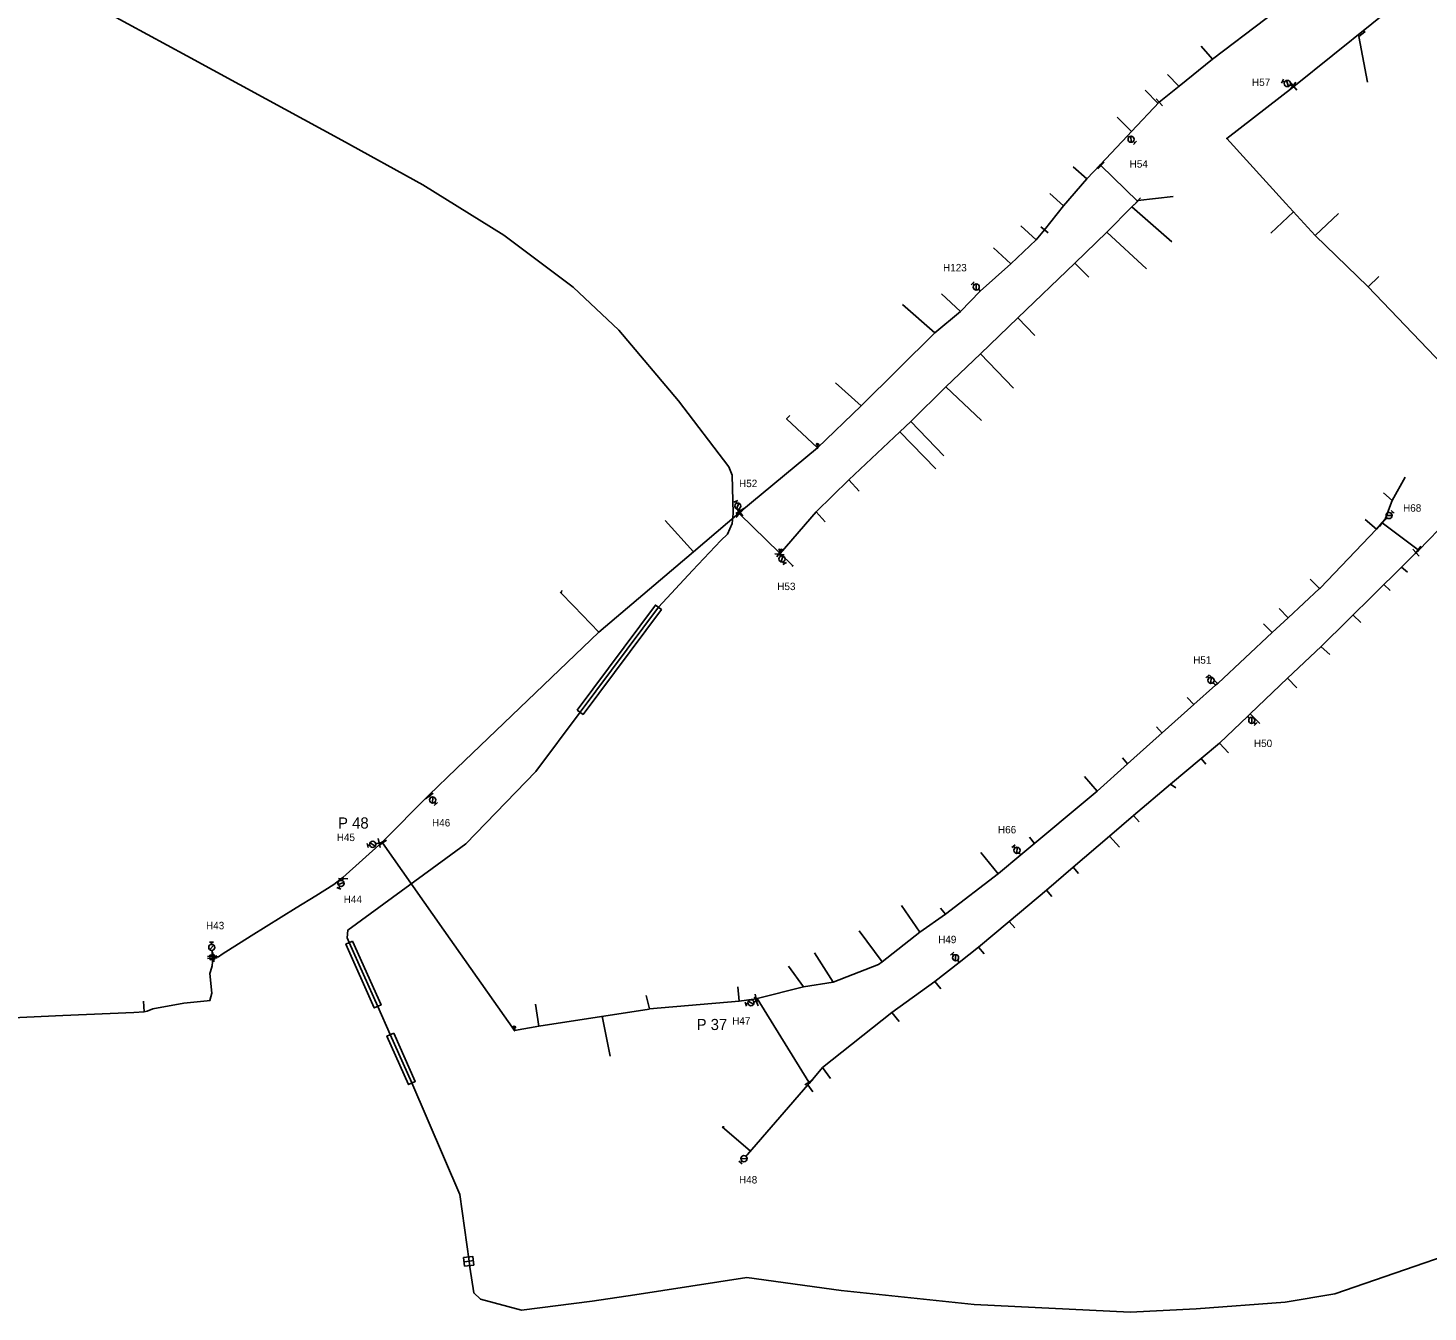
# Model space of a CAD drawing. Extents: x -548873 to -538270, y -1201997 to -1192514.
# Drawn here: x -546483.2 to -546105.6, y -1194944.2 to -1194597.8 of the extents above; entities that cross this region are included whole.
import ezdxf

# ---------------------------------------------------------------- set-up
doc = ezdxf.new("R2010")
doc.units = 0
for name, color, linetype in [('KN_HRAN_STÁTNÍ', 7, 'Continuous'), ('KN_PARC_Č', 7, 'Continuous'), ('KN_VKP_HRAN_SPORNÁ', 7, 'Continuous'), ('PK_HRAN_SPORNÁ', 7, 'Continuous'), ('PK_PARC_Čv', 7, 'Continuous'), ('Vrstva 29', 7, 'Continuous'), ('Vrstva 37', 7, 'Continuous'), ('Vrstva 39', 7, 'Continuous')]:
    doc.layers.add(name, color=color, linetype=linetype)

# ---------------------------------------------------------------- blocks, each defined once
blk = doc.blocks.new('160')
at = {"layer": 'KN_HRAN_STÁTNÍ'}
blk.add_circle((0, 0), 0.0458, dxfattribs=at)
blk = doc.blocks.new('147')
at = {"layer": 'KN_HRAN_STÁTNÍ'}
blk.add_line((0, 1.27), (0, -1.27), dxfattribs=at)
blk = doc.blocks.new('133')
at = {"layer": 'KN_HRAN_STÁTNÍ'}
for p, q in [((0.28, 0), (0, 0)), ((0.54, 0.58), (1.7, -0.58)), ((1.94, 0), (2.52, 0)), ((2.52, 0.58), (2.52, -0.58))]:
    blk.add_line(p, q, dxfattribs=at)
blk.add_circle((1.11, 0), 0.825, dxfattribs=at)
blk = doc.blocks.new('150')
at = {"layer": 'KN_HRAN_STÁTNÍ'}
blk.add_line((0, 1.27), (0, -1.27), dxfattribs=at)
blk = doc.blocks.new('128')
at = {"layer": 'KN_HRAN_STÁTNÍ'}
for p, q in [((-0.19, 1.06), (-0.43, 1.15)), ((-0.36, 0.84), (-0.19, 1.06)), ((-0.19, 1.06), (-0.02, 1.25)), ((-0.19, 1.06), (0, 0)), ((0.05, 0.95), (-0.19, 1.06)), ((-0.1, 1), (0.41, 0.91)), ((-0.07, 0.82), (0.17, 0.96)), ((0.17, 0.96), (-0.02, 1.13)), ((0.17, 0.96), (0, 0)), ((0.19, 1.21), (0.17, 0.96)), ((0.17, 0.96), (0.38, 1.08)), ((0.36, 0.77), (0.17, 0.96))]:
    blk.add_line(p, q, dxfattribs=at)

msp = doc.modelspace()

# ---------------------------------------------------------------- linework, layer by layer
at = {"layer": 'KN_PARC_Č'}
for points in [[(-546122.986, -1194598.456), (-546122.633, -1194598.83), (-546124.253, -1194600.048), (-546121.876, -1194612.409)], [(-546163.743, -1194606.156), (-546166.826, -1194602.721)], [(-546172.771, -1194613.509), (-546175.878, -1194610.38)], [(-546178.408, -1194618.175), (-546181.873, -1194614.569)], [(-546185.564, -1194625.718), (-546189.41, -1194621.875)], [(-546197.613, -1194638.468), (-546201.281, -1194635.229)], [(-546203.895, -1194645.758), (-546207.653, -1194642.446)], [(-546184.057, -1194644.482), (-546183.87, -1194644.37), (-546174.31, -1194643.22)], [(-546185.481, -1194646.007), (-546174.686, -1194655.498)], [(-546141.867, -1194647.364), (-546148.008, -1194653.176)], [(-546135.992, -1194653.742), (-546129.778, -1194647.874)], [(-546211.32, -1194654.964), (-546215.469, -1194651.136)], [(-546192.274, -1194652.901), (-546181.503, -1194662.751)], [(-546218.09, -1194661.404), (-546222.809, -1194657.141)], [(-546200.907, -1194661.253), (-546197.102, -1194665.049)], [(-546121.754, -1194667.633), (-546118.825, -1194664.814)], [(-546231.675, -1194674.228), (-546236.854, -1194669.543)], [(-546238.662, -1194680.015), (-546247.341, -1194672.412)], [(-546216.268, -1194676.004), (-546211.634, -1194680.771)], [(-546226.313, -1194685.65), (-546217.446, -1194694.965)], [(-546258.544, -1194699.677), (-546265.398, -1194693.53)], [(-546235.698, -1194694.605), (-546226.069, -1194703.721)], [(-546270.271, -1194711.09), (-546278.627, -1194703.224), (-546277.766, -1194702.301)], [(-546248.046, -1194706.704), (-546238.332, -1194716.698)], [(-546245.115, -1194703.951), (-546236.198, -1194713.176)], [(-546115.221, -1194725.284), (-546111.778, -1194718.979)], [(-546261.859, -1194719.676), (-546259.078, -1194722.71)], [(-546116.917, -1194730.186), (-546117.09, -1194730.018), (-546115.221, -1194725.284), (-546117.591, -1194723.222)], [(-546270.667, -1194728.284), (-546268.225, -1194730.992)], [(-546303.763, -1194739.095), (-546311.34, -1194730.65)], [(-546119.495, -1194732.956), (-546122.532, -1194730.391)], [(-546280.54, -1194739.38), (-546276.977, -1194742.888), (-546276.903, -1194742.82), (-546276.835, -1194742.894)], [(-546276.977, -1194742.888), (-546277.043, -1194742.963), (-546276.975, -1194743.036)], [(-546112.743, -1194743.216), (-546111.09, -1194744.591)], [(-546134.841, -1194749.019), (-546137.394, -1194746.495)], [(-546117.473, -1194747.911), (-546115.785, -1194749.567)], [(-546329.307, -1194760.744), (-546336.039, -1194753.781), (-546339.713, -1194749.945)], [(-546339.406, -1194750.266), (-546339.203, -1194749.54)], [(-546143.338, -1194756.926), (-546145.724, -1194754.403)], [(-546125.826, -1194756.202), (-546123.741, -1194758.129)], [(-546147.621, -1194760.91), (-546149.995, -1194758.488)], [(-546134.382, -1194764.695), (-546132.11, -1194766.84)], [(-546162.378, -1194774.635), (-546164.512, -1194772.411)], [(-546143.472, -1194773.159), (-546140.982, -1194775.757)], [(-546168.729, -1194780.313), (-546170.531, -1194778.423)], [(-546153.531, -1194782.778), (-546150.959, -1194785.389)], [(-546177.348, -1194788.02), (-546178.805, -1194786.356)], [(-546161.842, -1194790.712), (-546159.438, -1194793.34)], [(-546186.618, -1194796.308), (-546187.977, -1194794.661)], [(-546166.808, -1194794.883), (-546165.489, -1194796.415)], [(-546194.842, -1194803.658), (-546198.271, -1194799.72)], [(-546175.035, -1194801.793), (-546173.617, -1194802.8)], [(-546185.065, -1194810.22), (-546183.481, -1194811.951)], [(-546211.729, -1194817.756), (-546213.104, -1194816.118)], [(-546191.53, -1194815.782), (-546188.808, -1194818.78)], [(-546221.534, -1194825.94), (-546226.201, -1194820.236)], [(-546201.292, -1194824.178), (-546199.867, -1194825.921)], [(-546208.497, -1194830.375), (-546207.108, -1194832.062)], [(-546242.708, -1194841.687), (-546247.597, -1194834.516)], [(-546235.789, -1194836.871), (-546237.065, -1194835.268)], [(-546218.534, -1194838.815), (-546217.067, -1194840.498)], [(-546252.876, -1194849.682), (-546259.028, -1194841.391)], [(-546266.096, -1194855.173), (-546271.099, -1194847.246)], [(-546226.831, -1194845.794), (-546225.348, -1194847.523)], [(-546274.08, -1194856.427), (-546278.137, -1194850.861)], [(-546315.58, -1194862.436), (-546316.502, -1194858.753)], [(-546291.379, -1194860.351), (-546291.804, -1194856.479)], [(-546238.614, -1194855.023), (-546237.043, -1194857.026)], [(-546451.932, -1194863.229), (-546452.128, -1194860.291)], [(-546345.493, -1194867.09), (-546346.31, -1194861.12)], [(-546328.334, -1194864.416), (-546326.184, -1194875.204)], [(-546250.214, -1194863.344), (-546248.207, -1194865.843)], [(-546268.914, -1194878.261), (-546266.808, -1194881.224)], [(-546272.858, -1194882.905), (-546271.514, -1194884.812)], [(-546288.366, -1194900.764), (-546296.024, -1194894.205)], [(-546295.644, -1194894.53), (-546295.601, -1194894.022)]]:
    msp.add_lwpolyline(points, dxfattribs=at)
at = {"layer": 'KN_VKP_HRAN_SPORNÁ'}
for points in [[(-546141.811, -1194613.588), (-546120.765, -1194596.671), (-546115.756, -1194592.647), (-546107.535, -1194586.111), (-546091.8, -1194574.383), (-546081.422, -1194567.518), (-546074.38, -1194562.881), (-546061.572, -1194555.512), (-546054.438, -1194551.591), (-546051.299, -1194549.866), (-546041.333, -1194544.088), (-546029.151, -1194537.503), (-546017.951, -1194531.352), (-546014.467, -1194529.438), (-546003.219, -1194523.26), (-545995.607, -1194519.528), (-545984.581, -1194513.447), (-545967.893, -1194504.829), (-545932.842, -1194488.164), (-545928.87, -1194485.6)], [(-546126.397, -1194578.01), (-546136.167, -1194585.394), (-546149.224, -1194595.263), (-546163.743, -1194606.156), (-546172.754, -1194613.495), (-546178.09, -1194617.84)], [(-546159.838, -1194627.61), (-546141.901, -1194613.661), (-546141.811, -1194613.588)], [(-546178.09, -1194617.84), (-546185.563, -1194625.717), (-546186.67, -1194626.889), (-546194.034, -1194634.68)], [(-546086.47, -1194702.96), (-546103.514, -1194686.669), (-546103.668, -1194686.508), (-546121.816, -1194667.569), (-546135.992, -1194653.742), (-546143.948, -1194645.105), (-546159.838, -1194627.61)], [(-546194.034, -1194634.68), (-546197.613, -1194638.468), (-546203.895, -1194645.758), (-546209.04, -1194652.27)], [(-546194.034, -1194634.68), (-546193.82, -1194634.89)], [(-546193.82, -1194634.89), (-546183.999, -1194644.539)], [(-546183.999, -1194644.539), (-546183.936, -1194644.601), (-546185.481, -1194646.007), (-546192.274, -1194652.901), (-546200.907, -1194661.253), (-546216.268, -1194676.004), (-546226.312, -1194685.649), (-546235.691, -1194694.598), (-546245.114, -1194703.95), (-546248.046, -1194706.703), (-546261.859, -1194719.676), (-546270.667, -1194728.284), (-546280.358, -1194739.557)], [(-546209.04, -1194652.27), (-546211.319, -1194654.963), (-546218.087, -1194661.401), (-546226.373, -1194668.799), (-546231.675, -1194674.228), (-546238.662, -1194680.015), (-546258.544, -1194699.677), (-546270.244, -1194711.067)], [(-546270.244, -1194711.067), (-546291.22, -1194728.45)], [(-546291.534, -1194728.712), (-546303.758, -1194739.09)], [(-546291.22, -1194728.45), (-546291.534, -1194728.712)], [(-546291.35, -1194728.89), (-546291.534, -1194728.712)], [(-546280.54, -1194739.38), (-546291.35, -1194728.89)], [(-546117.978, -1194731.239), (-546116.913, -1194730.182)], [(-546108.134, -1194738.726), (-546099.982, -1194730.283)], [(-546286.559, -1194859.614), (-546274.08, -1194856.427), (-546266.095, -1194855.173), (-546266.017, -1194855.161), (-546253.86, -1194850.456), (-546252.877, -1194849.683), (-546242.708, -1194841.687), (-546235.786, -1194836.869), (-546221.498, -1194825.912), (-546215.443, -1194820.857), (-546194.843, -1194803.659), (-546186.618, -1194796.308), (-546168.731, -1194780.315), (-546162.922, -1194775.122), (-546162.381, -1194774.638), (-546162.227, -1194774.5), (-546147.621, -1194760.91), (-546143.338, -1194756.926), (-546134.841, -1194749.019), (-546134.724, -1194748.911), (-546119.495, -1194732.956), (-546117.978, -1194731.239)], [(-546117.978, -1194731.239), (-546117.95, -1194731.26)], [(-546117.95, -1194731.26), (-546108.295, -1194738.609)], [(-546303.758, -1194739.09), (-546329.307, -1194760.744)], [(-546280.54, -1194739.38), (-546280.358, -1194739.557)], [(-546272.438, -1194882.421), (-546268.908, -1194878.254), (-546250.214, -1194863.344), (-546238.614, -1194855.023), (-546232.028, -1194849.859), (-546226.83, -1194845.793), (-546218.535, -1194838.816), (-546208.497, -1194830.375), (-546201.292, -1194824.178), (-546191.532, -1194815.783), (-546185.065, -1194810.22), (-546175.034, -1194801.792), (-546166.808, -1194794.883), (-546161.842, -1194790.712), (-546161.722, -1194790.611), (-546154.291, -1194783.505), (-546153.531, -1194782.778), (-546143.472, -1194773.159), (-546134.374, -1194764.687), (-546112.744, -1194743.217), (-546108.807, -1194739.309)], [(-546108.807, -1194739.309), (-546108.134, -1194738.726)], [(-546108.295, -1194738.609), (-546108.134, -1194738.726)], [(-546329.307, -1194760.744), (-546367.632, -1194797.587), (-546375.109, -1194804.775), (-546387.734, -1194817.409)], [(-546387.734, -1194817.409), (-546398.318, -1194827)], [(-546387.734, -1194817.409), (-546387.6, -1194817.63)], [(-546387.6, -1194817.63), (-546371.035, -1194841.207), (-546352.031, -1194868.254)], [(-546398.318, -1194827), (-546400.74, -1194828.82), (-546405.63, -1194831.94), (-546410.91, -1194835.12), (-546423.01, -1194842.72), (-546430.87, -1194847.61), (-546431.87, -1194848.33), (-546431.94, -1194848.35), (-546432.725, -1194848.39), (-546433.27, -1194848.42)], [(-546433.56, -1194848.16), (-546433.603, -1194847.112)], [(-546487.382, -1194864.802), (-546473.827, -1194864.211), (-546454.657, -1194863.363), (-546451.932, -1194863.229), (-546451.08, -1194862.99), (-546449.54, -1194862.42), (-546441.25, -1194860.87), (-546434.88, -1194860.24), (-546434.166, -1194860.169), (-546433.7, -1194858.21), (-546434.19, -1194852.88), (-546433.98, -1194852.29), (-546433.56, -1194850.76), (-546433.493, -1194849.74), (-546433.501, -1194849.449), (-546433.52, -1194848.74)], [(-546433.54, -1194848.46), (-546433.56, -1194848.16)], [(-546433.27, -1194848.42), (-546433.54, -1194848.46)], [(-546433.52, -1194848.74), (-546433.54, -1194848.46)], [(-546352.031, -1194868.254), (-546345.493, -1194867.09), (-546315.687, -1194862.445), (-546315.58, -1194862.436), (-546291.379, -1194860.351), (-546286.856, -1194859.659)], [(-546286.856, -1194859.659), (-546286.559, -1194859.614)], [(-546272.576, -1194882.196), (-546286.559, -1194859.614)], [(-546289.261, -1194901.795), (-546289.184, -1194901.707), (-546272.858, -1194882.905), (-546272.438, -1194882.421)], [(-546272.576, -1194882.196), (-546272.438, -1194882.421)]]:
    msp.add_lwpolyline(points, dxfattribs=at)
at = {"layer": 'PK_HRAN_SPORNÁ'}
for points in [[(-546364.251, -1194930.494), (-546366.75, -1194912.52), (-546379.68, -1194882.4), (-546385.51, -1194869.33), (-546388.91, -1194861.76), (-546396.58, -1194844.54), (-546397.132, -1194843.25), (-546396.96, -1194841.17), (-546370.57, -1194821.84), (-546365.1, -1194817.88), (-546346.25, -1194798.34), (-546334.333, -1194782.39), (-546313.18, -1194754.08), (-546303.96, -1194744.18), (-546296.32, -1194736.07), (-546294.54, -1194734.33), (-546293.34, -1194731.48), (-546292.99, -1194728.78), (-546293.31, -1194718.42), (-546294.16, -1194716.21), (-546307.73, -1194698.38), (-546323.83, -1194679.28), (-546336.23, -1194667.67), (-546354.85, -1194653.7), (-546376.78, -1194640.1), (-546398.61, -1194628.04), (-546419.12, -1194616.9), (-546440.4, -1194605.33), (-546466.88, -1194590.91)], [(-546364.252, -1194930.494), (-546364.03, -1194932.09), (-546362.99, -1194939.04), (-546361.17, -1194940.7), (-546350.08, -1194943.7), (-546331.05, -1194941.22), (-546319.52, -1194939.57), (-546289.35, -1194934.87), (-546263.89, -1194938.41), (-546227.98, -1194942.13), (-546185.92, -1194944.18), (-546168.17, -1194943.34), (-546144.156, -1194941.519), (-546130.7, -1194939.27), (-546079.57, -1194921.64)]]:
    msp.add_lwpolyline(points, dxfattribs=at)
at = {"layer": 'PK_PARC_Čv'}
for points in [[(-546141.901, -1194613.661), (-546142.06, -1194613.44), (-546142.5, -1194613.25)], [(-546186.67, -1194626.889), (-546186.51, -1194627.04)], [(-546226.373, -1194668.799), (-546226.68, -1194668.47)], [(-546291.04, -1194728.301), (-546291.21, -1194728.11), (-546291.34, -1194727.8)], [(-546116.913, -1194730.182), (-546116.862, -1194730.131)], [(-546280.358, -1194739.557), (-546280.55, -1194739.78), (-546280.39, -1194740.07)], [(-546162.922, -1194775.122), (-546163.403, -1194774.587)], [(-546154.291, -1194783.505), (-546153.938, -1194783.839)], [(-546375.109, -1194804.775), (-546374.994, -1194804.979), (-546374.816, -1194805.197)], [(-546387.875, -1194817.537), (-546389.166, -1194817.786)], [(-546215.443, -1194820.857), (-546215.761, -1194820.473)], [(-546398.318, -1194827), (-546398.223, -1194827.265), (-546398.355, -1194827.553)], [(-546433.603, -1194847.112), (-546433.61, -1194846.93)], [(-546434.22, -1194847.88), (-546432.994, -1194847.828), (-546432.94, -1194849.08), (-546434.11, -1194849.13), (-546434.22, -1194847.88)], [(-546232.028, -1194849.859), (-546232.33, -1194849.473)], [(-546286.201, -1194860.192), (-546286.808, -1194860.373), (-546287.167, -1194860.464)], [(-546289.261, -1194901.795), (-546289.394, -1194901.949)], [(-546365.743, -1194929.458), (-546363.275, -1194929.189), (-546363.02, -1194931.53), (-546365.488, -1194931.799), (-546365.743, -1194929.458)]]:
    msp.add_lwpolyline(points, dxfattribs=at)
at = {"layer": 'Vrstva 37'}
for points in [[(-546335.134, -1194781.791), (-546313.981, -1194753.481), (-546312.379, -1194754.679), (-546333.532, -1194782.989), (-546335.134, -1194781.791)], [(-546395.667, -1194844.133), (-546387.997, -1194861.353), (-546389.823, -1194862.167), (-546397.493, -1194844.947), (-546395.667, -1194844.133)], [(-546384.597, -1194868.923), (-546378.767, -1194881.993), (-546380.593, -1194882.807), (-546386.423, -1194869.737), (-546384.597, -1194868.923)]]:
    msp.add_lwpolyline(points, dxfattribs=at)

# ---------------------------------------------------------------- block references
at = {"layer": 'PK_PARC_Čv'}
for name, p, xscale, yscale, rotation in [('133', (-546142.5, -1194613.25), 1.0225848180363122, 1.0225848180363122, 154.18102564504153), ('150', (-546142.06, -1194613.44), 1.000000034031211, 1.0000000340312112, -38.000000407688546), ('133', (-546186.51, -1194627.04), 1.00000000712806, 1.00000000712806, -43.0000005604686), ('133', (-546226.68, -1194668.47), 1.0000000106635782, 1.0000000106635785, 134.00000165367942), ('133', (-546291.34, -1194727.8), 1.0000000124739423, 1.000000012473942, 112.99999954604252), ('150', (-546291.21, -1194728.11), 0.9999999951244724, 0.9999999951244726, -56.999998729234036), ('133', (-546116.862, -1194730.131), 1.0000000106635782, 1.0000000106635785, 45.99999834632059), ('150', (-546280.55, -1194739.78), 1.000000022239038, 1.0000000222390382, 85.00000001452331), ('133', (-546280.39, -1194740.07), 1.0000000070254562, 1.0000000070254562, -61.000001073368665), ('133', (-546163.403, -1194774.587), 1.0000000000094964, 1.0000000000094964, 132.0000013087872), ('133', (-546153.938, -1194783.839), 1.00000000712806, 1.00000000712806, -43.0000005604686), ('150', (-546374.994, -1194804.979), 1.000000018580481, 1.000000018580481, -54.99999976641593), ('133', (-546374.816, -1194805.197), 1.0000000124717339, 1.0000000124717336, -49.99999868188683), ('133', (-546389.166, -1194817.786), 1.0060666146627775, 1.0060666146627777, -167.3452647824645), ('150', (-546388.52, -1194817.661), 1.0060666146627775, 1.0060666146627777, 12.654735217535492), ('133', (-546215.761, -1194820.473), 1.0000000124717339, 1.0000000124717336, 130.0000013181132), ('133', (-546398.355, -1194827.553), 0.9999999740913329, 0.9999999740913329, -114.00000060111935), ('150', (-546398.223, -1194827.265), 1.00000001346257, 1.0000000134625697, -91.99999990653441), ('133', (-546433.61, -1194846.93), 0.9999999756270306, 0.9999999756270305, 93.00000001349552), ('133', (-546232.33, -1194849.473), 1.000000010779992, 1.0000000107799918, 128.99999891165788), ('133', (-546287.167, -1194860.464), 0.999999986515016, 0.9999999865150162, -164.99999987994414), ('150', (-546286.808, -1194860.373), 1.0365458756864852, 1.0365458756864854, 21.97149085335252), ('133', (-546289.394, -1194901.949), 1.0000000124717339, 1.0000000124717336, -130.0000013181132)]:
    msp.add_blockref(name, p, dxfattribs=dict(at, xscale=xscale, yscale=yscale, rotation=rotation))
at = {"layer": 'Vrstva 29'}
for name, p, xscale, yscale, rotation in [('147', (-546141.811, -1194613.588), 1.000000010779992, 1.0000000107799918, -141.00000108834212), ('147', (-546178.09, -1194617.84), 1.00000000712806, 1.00000000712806, -136.99999943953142), ('160', (-546159.838, -1194627.61), 1.0000000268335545, 1.0000000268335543, 86.00000028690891), ('147', (-546193.82, -1194634.89), 1.0000000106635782, 1.0000000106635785, 135.99999834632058), ('160', (-546194.034, -1194634.68), 1.00000001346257, 1.0000000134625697, -178.0000000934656), ('147', (-546183.999, -1194644.539), 1.0000000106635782, 1.0000000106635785, 135.99999834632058), ('147', (-546209.04, -1194652.27), 1.000000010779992, 1.0000000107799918, -128.99999891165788), ('160', (-546270.244, -1194711.067), 1.0000000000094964, 1.0000000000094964, -137.9999986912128), ('147', (-546291.35, -1194728.89), 1.0000000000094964, 1.0000000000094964, 137.9999986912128), ('147', (-546291.22, -1194728.45), 1.0000000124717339, 1.0000000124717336, -139.99999868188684), ('160', (-546291.534, -1194728.712), 1.000000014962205, 1.0000000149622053, 179.0000000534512), ('147', (-546117.95, -1194731.26), 0.9999999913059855, 0.9999999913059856, -37.00000193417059), ('160', (-546116.913, -1194730.182), 0.999999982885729, 0.9999999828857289, 45), ('160', (-546117.978, -1194731.239), 1.00000000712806, 1.00000000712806, 46.99999943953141), ('147', (-546108.295, -1194738.609), 1.000000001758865, 1.000000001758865, 144.00000066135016), ('160', (-546303.758, -1194739.09), 1.0000000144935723, 1.0000000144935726, -139.00000089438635), ('147', (-546280.54, -1194739.38), 1.000000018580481, 1.000000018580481, 144.99999976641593), ('160', (-546280.358, -1194739.557), 1.0002788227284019, 1.0002788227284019, -176.70930040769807), ('147', (-546108.807, -1194739.309), 1.00000000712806, 1.00000000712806, -136.99999943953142), ('160', (-546108.134, -1194738.726), 1.0011217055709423, 1.0011217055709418, -173.41739016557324), ('160', (-546329.307, -1194760.744), 1.00000000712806, 1.00000000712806, -136.99999943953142), ('147', (-546387.6, -1194817.63), 0.9999999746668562, 0.999999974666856, 124.00000045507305), ('160', (-546387.734, -1194817.409), 1.0092050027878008, 1.0092050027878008, 168.88308178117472), ('160', (-546398.318, -1194827), 1.0000000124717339, 1.0000000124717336, -139.99999868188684), ('160', (-546433.603, -1194847.112), 0.9999999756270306, 0.9999999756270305, -86.99999998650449), ('147', (-546433.27, -1194848.42), 1.0011217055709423, 1.0011217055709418, -173.41739016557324), ('147', (-546433.56, -1194848.16), 1.0000000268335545, 1.0000000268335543, 93.99999971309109), ('147', (-546433.52, -1194848.74), 0.9999999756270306, 0.9999999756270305, 93.00000001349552), ('160', (-546433.54, -1194848.46), 1.0000000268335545, 1.0000000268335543, 93.99999971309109), ('147', (-546286.856, -1194859.659), 1.008377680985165, 1.0083776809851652, -168.37362119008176), ('160', (-546286.559, -1194859.614), 1.0045862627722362, 1.0045862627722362, 13.174090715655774), ('160', (-546352.031, -1194868.254), 1.0000000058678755, 1.0000000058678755, 68.00000099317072), ('147', (-546272.576, -1194882.196), 0.9999999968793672, 0.9999999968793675, 122.00000027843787), ('160', (-546272.438, -1194882.421), 1.0000000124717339, 1.0000000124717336, -130.0000013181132), ('160', (-546289.261, -1194901.795), 1.0000000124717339, 1.0000000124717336, 49.99999868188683), ('147', (-546364.251, -1194930.494), 0.9999999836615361, 0.9999999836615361, 98.00000038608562)]:
    msp.add_blockref(name, p, dxfattribs=dict(at, xscale=xscale, yscale=yscale, rotation=rotation))
at = {"layer": 'Vrstva 39'}
for p in [(-546270.244, -1194711.067), (-546280.358, -1194739.557), (-546352.031, -1194868.254)]:
    msp.add_blockref('128', p, dxfattribs=at)

# ---------------------------------------------------------------- texts
at = {"layer": 'PK_PARC_Čv'}
for s, height, p in [('H57', 2, (-546153.07, -1194613.44)), ('H54', 2, (-546186.07, -1194635.46)), ('H123', 2, (-546236.41, -1194663.44)), ('H52', 2, (-546291.44, -1194721.65)), ('H68', 2, (-546112.322, -1194728.271)), ('H53', 2, (-546281.13, -1194749.43)), ('H51', 2, (-546168.943, -1194769.277)), ('H50', 2, (-546152.538, -1194791.769)), ('P 48', 3, (-546399.606, -1194813.756)), ('H46', 2, (-546374.256, -1194813.197)), ('H66', 2, (-546221.591, -1194815.053)), ('H45', 2, (-546399.956, -1194817.136)), ('H44', 2, (-546398.075, -1194833.833)), ('H43', 2, (-546435.21, -1194840.92)), ('H49', 2, (-546237.73, -1194844.683)), ('P 37', 3, (-546302.887, -1194868.114)), ('H47', 2, (-546293.297, -1194866.644)), ('H48', 2, (-546291.444, -1194909.509))]:
    msp.add_text(s, height=height, dxfattribs=at).set_placement(p)

doc.saveas('drawing.dxf')
